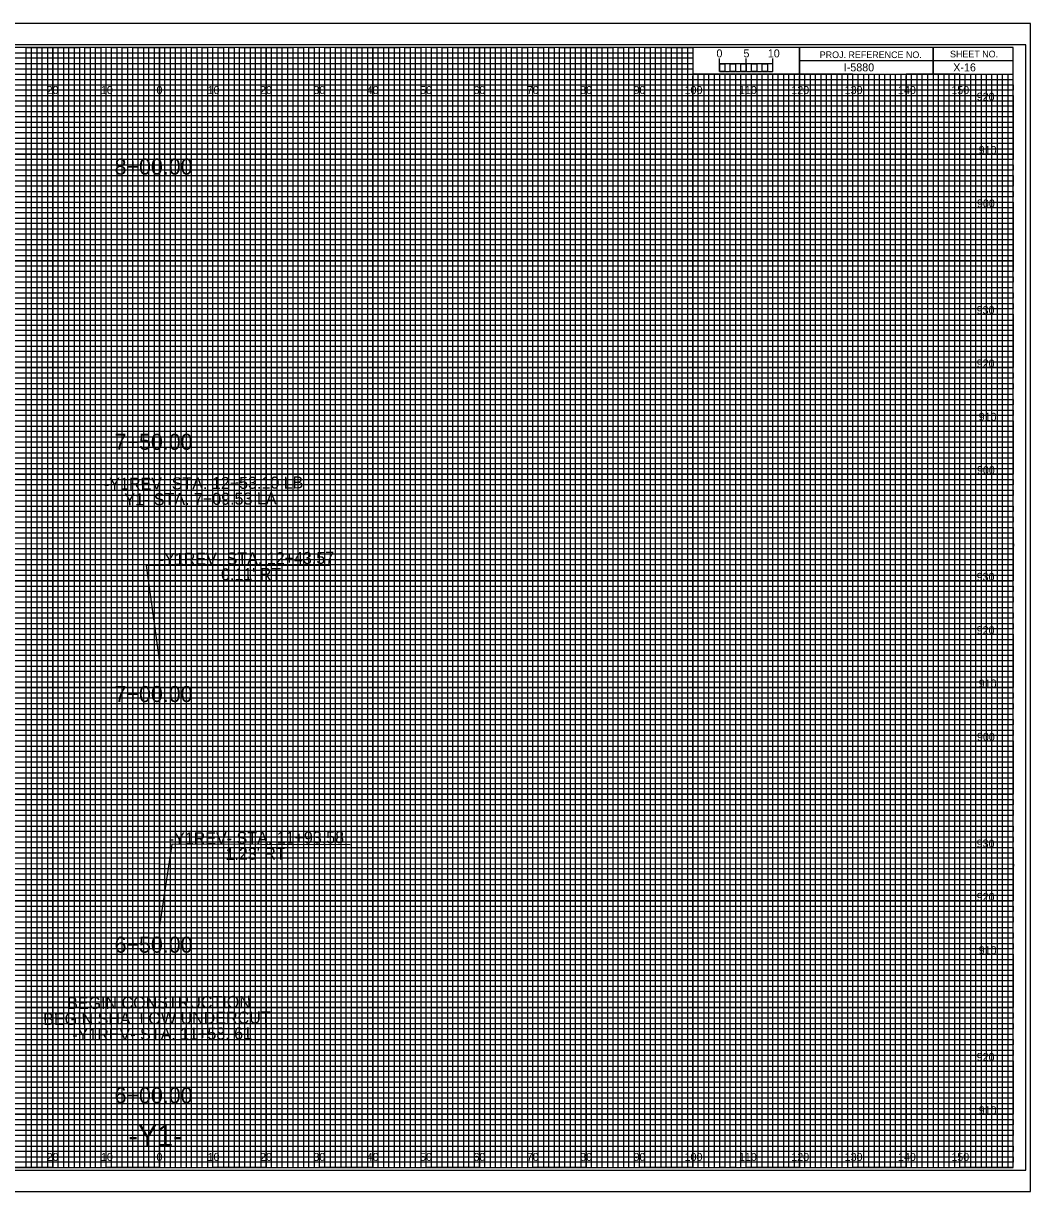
# Model space of a CAD drawing. Extents: x -13 to 323, y -4 to 214.
# Drawn here: x 134.5 to 323.3, y -4.5 to 214.5 of the extents above; entities that cross this region are included whole.
import ezdxf

# ---------------------------------------------------------------- set-up
doc = ezdxf.new("R2010")
doc.units = 0
for name, color, linetype in [('Exist XS Center Line Elevation Label', 7, 'Continuous'), ('Prop XS Alignment Label', 7, 'Continuous'), ('Prop XS Bar Scale Labels', 7, 'Continuous'), ('Prop XS Elevation Labels', 7, 'Continuous'), ('Prop XS Project Number', 7, 'Continuous'), ('Prop XS SE Text', 7, 'Continuous'), ('Prop XS Sheet Number', 7, 'Continuous'), ('Prop XS Station Labels', 7, 'Continuous'), ('Sheet Cross Section CELL', 7, 'Continuous'), ('Sheet Cross Section Grid Major CELL', 7, 'Continuous'), ('Sheet Cross Section Grid Middle CELL', 7, 'Continuous'), ('Sheet Cross Section Grid Minor 1 CELL', 7, 'Continuous'), ('Sheet Cross Section Grid Minor 2 CELL', 7, 'Continuous'), ('Sheet Cross Section Scale CELL', 7, 'Continuous'), ('Sheet Cutting Line CELL', 7, 'Continuous'), ('Sheet DOT Grid CELL', 7, 'Continuous'), ('Sheet Plot Border Inside CELL', 7, 'Continuous'), ('Sheet Plot Border Outside CELL', 7, 'Continuous')]:
    doc.layers.add(name, color=color, linetype=linetype)

msp = doc.modelspace()

# ---------------------------------------------------------------- linework, layer by layer
at = {"layer": 'Prop XS SE Text'}
for p, q in [((191.87, 112.88), (157.52, 112.88)), ((157.52, 112.88), (160, 94.74)), ((162.31, 60.64), (160, 45.32)), ((195.77, 60.51), (162.31, 60.64))]:
    msp.add_line(p, q, dxfattribs=at)
at = {"layer": 'Sheet Cross Section CELL'}
for p, q in [((305, 210), (305, 205)), ((305, 205), (305, 210)), ((280, 207.5), (280, 205)), ((320, 207.49), (280, 207.49)), ((280, 205), (320, 205))]:
    msp.add_line(p, q, dxfattribs=at)
for points in [[(320, 210), (0, 210), (0, 0), (320, 0)], [(280, 210), (260, 210), (260, 205.03), (280, 205.03)], [(320, 210), (280, 210), (280, 205), (320, 205)]]:
    msp.add_lwpolyline(points, close=True, dxfattribs=at)
at = {"layer": 'Sheet Cross Section Grid Major CELL'}
for p, q in [((150, 210), (140, 210)), ((140, 210), (140, 0)), ((150, 0), (150, 210)), ((170, 210), (160, 210)), ((160, 210), (160, 0)), ((170, 0), (170, 210)), ((190, 210), (180, 210)), ((180, 210), (180, 0)), ((190, 0), (190, 210)), ((210, 210), (200, 210)), ((200, 210), (200, 0)), ((210, 0), (210, 210)), ((230, 210), (220, 210)), ((220, 210), (220, 0)), ((230, 0), (230, 210)), ((250, 210), (240, 210)), ((240, 210), (240, 0)), ((250, 0), (250, 210)), ((260, 210), (260, 0)), ((270, 0), (270, 205)), ((290, 205), (280, 205)), ((280, 205), (280, 0)), ((290, 0), (290, 205)), ((310, 205), (300, 205)), ((300, 205), (300, 0)), ((310, 0), (310, 205)), ((140, 0), (130, 0)), ((160, 0), (150, 0)), ((180, 0), (170, 0)), ((200, 0), (190, 0)), ((220, 0), (210, 0)), ((240, 0), (230, 0)), ((260, 0), (250, 0)), ((280, 0), (270, 0)), ((300, 0), (290, 0)), ((320, 0), (310, 0)), ((320, 0), (320, 0))]:
    msp.add_line(p, q, dxfattribs=at)
for points in [[(0, 200), (320, 200), (320, 190), (0, 190)], [(0, 180), (320, 180), (320, 170), (0, 170)], [(0, 160), (320, 160), (320, 150), (0, 150)], [(0, 140), (320, 140), (320, 130), (0, 130)], [(0, 120), (320, 120), (320, 110), (0, 110)], [(0, 100), (320, 100), (320, 90), (0, 90)], [(0, 80), (320, 80), (320, 70), (0, 70)], [(0, 60), (320, 60), (320, 50), (0, 50)], [(0, 40), (320, 40), (320, 30), (0, 30)], [(0, 20), (320, 20), (320, 10), (0, 10)]]:
    msp.add_lwpolyline(points, dxfattribs=at)
at = {"layer": 'Sheet Cross Section Grid Middle CELL'}
for points in [[(125, 0), (135, 0), (135, 210), (145, 210), (145, 0), (155, 0), (155, 210), (165, 210), (165, 0), (175, 0), (175, 210), (185, 210), (185, 0), (195, 0), (195, 210), (205, 210), (205, 0), (215, 0), (215, 210), (225, 210), (225, 0), (235, 0), (235, 210), (245, 210), (245, 0), (255, 0), (255, 210), (259.93, 210), (260, 210), (260, 205), (264.99, 205), (264.99, 0), (275, 0), (275, 205), (285, 205), (285, 0), (295, 0), (295, 205), (305, 205), (305, 0), (315, 0), (315, 205)], [(0, 205), (275, 205)], [(0, 185), (320, 185), (320, 195), (0, 195)], [(0, 165), (320, 165), (320, 175), (0, 175)], [(0, 145), (320, 145), (320, 155), (0, 155)], [(0, 125), (320, 125), (320, 135), (0, 135)], [(0, 105), (320, 105), (320, 115), (0, 115)], [(0, 85), (320, 85), (320, 95), (0, 95)], [(0, 65), (320, 65), (320, 75), (0, 75)], [(0, 45), (320, 45), (320, 55), (0, 55)], [(0, 25), (320, 25), (320, 35), (0, 35)], [(0, 5), (320, 5), (320, 15), (0, 15)]]:
    msp.add_lwpolyline(points, dxfattribs=at)
at = {"layer": 'Sheet Cross Section Grid Minor 1 CELL'}
for p, q in [((0, 209), (260, 209)), ((260, 209), (260, 207.98)), ((260, 207.98), (0, 207.98)), ((0, 207), (260, 207)), ((260, 205.89), (0, 205.89)), ((260, 207), (260, 205.89)), ((0, 204), (320, 204))]:
    msp.add_line(p, q, dxfattribs=at)
for points in [[(0, 203), (270, 203), (320, 203), (320, 202), (0, 202)], [(0, 201), (320, 201), (320, 199), (0, 199)], [(0, 198), (320, 198), (320, 197), (0, 196.98)], [(0, 196), (320, 196), (320, 194), (0, 194)], [(0, 193), (320, 193), (320, 192), (0, 192)], [(0, 191), (320, 191), (320, 189), (0, 189)], [(0, 188), (320, 188), (320, 187), (0, 187)], [(0, 186), (320, 186), (320, 184), (0, 184)], [(0, 183), (320, 183), (320, 182), (0, 182)], [(0, 181), (320, 181), (320, 179), (0, 179)], [(0, 178), (320, 178), (320, 177), (0, 177)], [(0, 176), (320, 176), (320, 173.95), (320, 173), (320, 172), (0, 172)], [(0, 174), (320, 174), (320, 173), (0, 173)], [(0, 171), (320, 171), (320, 169), (0, 169.03)], [(0, 169.03), (320, 169), (320, 168), (0, 168)], [(0, 167), (320, 167), (320, 166), (0, 166)], [(0, 164), (320, 164), (320, 163), (0, 163)], [(0, 162), (320, 162), (320, 161), (0, 161)], [(-0.07, 158.89), (320, 158.89), (320, 157.88), (-0.07, 157.88)], [(0, 157), (320, 157), (320, 156), (0, 156)], [(0, 154), (320, 154), (320, 153), (0, 153)], [(0, 152), (320, 152), (320, 151), (0, 151)], [(0, 149), (320, 149), (320, 148), (0, 148)], [(0, 147), (320, 147), (320, 146), (0, 146)], [(0, 144), (320, 144), (320, 143), (0, 143)], [(0, 142), (320, 142), (320, 141), (0, 141)], [(0, 139), (320, 139), (319.99, 137.98), (0, 138)], [(0, 137), (320, 137), (320, 136), (0, 136)], [(0, 134), (320, 134), (320, 133), (0, 133)], [(0, 132), (320, 132), (320, 131), (0, 131)], [(0, 129), (320, 129), (320, 128), (0, 128)], [(0, 127), (320, 127), (320, 126), (0, 126)], [(0, 124), (320, 124), (320, 123), (0, 123)], [(0, 122), (320, 122), (320, 121), (0, 121)], [(0, 119), (320, 119), (320, 118), (0, 118)], [(0, 116.99), (320.07, 116.91), (320, 116), (0, 116)], [(0, 114), (320, 114), (320, 113), (0, 113)], [(0, 112), (320, 112), (320, 111), (0, 111)], [(0, 109), (320, 109), (320, 108), (0, 108)], [(0, 107), (320, 107), (320, 106), (0, 106)], [(0, 104), (320, 104), (320, 103), (0, 103)], [(0, 102), (320, 102), (320, 101), (0, 101)], [(0, 99), (320, 99), (320, 98), (0, 98)], [(0, 97), (320, 97), (320, 96), (0, 96)], [(0, 94), (320, 94), (320, 93), (0, 93)], [(0, 92), (320, 92), (320, 91), (0, 91)], [(0, 89), (320, 89), (320, 88), (0, 88)], [(0, 87), (320, 87), (320, 86), (0, 86)], [(0, 84), (320, 84), (320, 83), (0, 83)], [(0, 82), (320, 82), (320, 81), (0, 81)], [(0, 79), (320, 79), (319.99, 77.98), (0, 78)], [(0, 77), (320, 77), (320, 76), (0, 76)], [(0, 74), (320, 74), (320, 73), (0, 73)], [(0, 72), (320, 72), (320, 71), (0, 71)], [(0, 69), (320, 69), (320, 68), (0, 68)], [(0, 67), (320, 67), (320, 66), (0, 66)], [(0, 64), (320, 64), (320, 63), (0, 63)], [(0, 62), (320, 62), (320, 61), (0, 61)], [(0, 59), (320, 59), (320, 58), (0, 58)], [(0, 56.99), (320.07, 56.91), (320, 56), (0, 56)], [(0, 54), (320, 54), (320, 53), (0, 53)], [(0, 52), (320, 52), (320, 51), (0, 51)], [(0, 49), (320, 49), (320, 48), (0, 48)], [(0, 47), (320, 47), (320, 46), (0, 46)], [(0, 44), (320, 44), (320, 43), (0, 43)], [(0, 42), (320, 42), (320, 41), (0, 41)], [(0, 39), (320, 39), (320, 38), (0, 38)], [(0, 37), (320, 37), (320, 36), (0, 36)], [(0, 34), (320, 34), (320, 33), (0, 33)], [(0, 32), (320, 32), (320, 31), (0, 31)], [(0, 29), (320, 29), (320, 28), (0, 28)], [(0, 27), (320, 27), (320, 26), (0, 26)], [(0, 24), (320, 24), (320, 23), (0, 23)], [(0, 22), (320, 22), (320, 21), (0, 21)], [(0, 19), (320, 19), (320, 18), (0, 18)], [(0, 17), (320, 17), (320, 16), (0, 16)], [(0, 14), (320, 14), (320, 13), (0, 13)], [(0, 12), (320, 12), (320, 11), (0, 11)], [(0, 9), (320, 9), (320, 8), (0, 8)], [(0, 7), (320, 7), (320, 6), (0, 6)], [(0, 4), (320, 4), (320, 3), (0, 3)], [(0, 2), (320, 2), (320, 1), (0, 1)]]:
    msp.add_lwpolyline(points, dxfattribs=at)
at = {"layer": 'Sheet Cross Section Grid Minor 2 CELL'}
for p, q in [((267, 205), (266.01, 205)), ((266.01, 205), (266.01, 0)), ((267, 0), (267, 205)), ((269, 205), (268, 205)), ((268, 205), (268, 0)), ((269, 0), (269, 205)), ((266.01, 0), (265, 0)), ((268, 0), (267, 0))]:
    msp.add_line(p, q, dxfattribs=at)
for points in [[(135, 0), (136, 0), (136, 210), (137, 210), (137, 0)], [(137, 0), (138, 0), (138, 210), (139, 210), (139, 0)], [(140, 0), (141, 0), (141, 210), (142, 210), (142, 0)], [(142, 0), (143, 0), (143, 210), (144, 210), (144, 0)], [(145, 0), (146, 0), (146, 210), (147, 210), (147, 0)], [(147, 0), (148, 0), (148, 210), (149, 210), (149, 0)], [(150, 0), (151, 0), (151, 210), (152, 210), (152, 0)], [(152, 0), (153, 0), (153, 210), (154, 210), (154, 0)], [(155, 0), (156, 0), (156, 210), (157, 210), (157, 0)], [(157, 0), (158, 0), (158, 210), (159, 210), (159, 0)], [(160, 0), (161, 0), (161, 210), (162, 210), (162, 0)], [(162, 0), (163, 0), (163, 210), (164, 210), (164, 0)], [(165, 0), (166, 0), (166, 210), (167, 210), (167, 0)], [(167, 0), (168, 0), (168, 210), (169, 210), (169, 0)], [(170, 0), (171, 0), (171, 210), (172, 210), (172, 0)], [(172, 0), (173, 0), (173, 210), (174, 210), (174, 0)], [(175, 0), (176, 0), (176, 210), (177, 210), (177, 0)], [(177, 0), (178, 0), (178, 210), (179, 210), (179, 0)], [(180, 0), (181, 0), (181, 210), (182, 210), (182, 0)], [(182, 0), (183, 0), (183, 210), (184, 210), (184, 0)], [(185, 0), (186, 0), (186, 210), (187, 210), (187, 0)], [(187, 0), (188, 0), (188, 210), (189, 210), (189, 0)], [(190, 0), (191, 0), (191, 210), (192, 210), (192, 0)], [(192, 0), (193, 0), (193, 210), (194, 210), (194, 0)], [(195, 0), (196, 0), (196, 210), (197, 210), (197, 0)], [(197, 0), (198, 0), (198, 210), (199, 210), (199, 0)], [(200, 0), (201, 0), (201, 210), (202, 210), (202, 0)], [(202, 0), (203, 0), (203, 210), (204, 210), (204, 0)], [(205, 0), (206, 0), (206, 210), (207, 210), (207, 0)], [(207, 0), (208, 0), (208, 210), (209, 210), (209, 0)], [(210, 0), (211, 0), (211, 210), (212, 210), (212, 0)], [(212, 0), (213, 0), (213, 210), (214, 210), (214, 0)], [(215, 0), (216, 0), (216, 210), (217, 210), (217, 0)], [(217, 0), (218, 0), (218, 210), (219, 210), (219, 0)], [(220, 0), (221, 0), (221, 210), (222, 210), (222, 0)], [(222, 0), (223, 0), (223, 210), (224, 210), (224, 0)], [(225, 0), (226, 0), (226, 210), (227, 210), (227, 0)], [(227, 0), (228, 0), (228, 210), (229, 210), (229, 0)], [(230, 0), (231, 0), (231, 210), (232, 210), (232, 0)], [(232, 0), (233, 0), (233, 210), (234, 210), (234, 0)], [(235, 0), (236, 0), (236, 210), (237, 210), (237, 0)], [(237, 0), (238, 0), (238, 210), (239, 210), (239, 0)], [(240, 0), (241, 0), (241, 210), (242, 210), (242, 0)], [(242, 0), (243, 0), (243, 210), (244, 210), (244, 0)], [(245, 0), (246, 0), (246, 210), (247, 210), (247, 0)], [(247, 0), (248, 0), (248, 210), (249, 210), (249, 0)], [(250, 0), (251, 0), (251, 210), (252, 210), (252, 0)], [(252, 0), (253, 0), (253, 210), (254, 210), (254, 0)], [(255, 0), (256, 0), (256, 210), (257, 210), (257, 0)], [(257, 0), (258, 0), (258, 210), (259, 210), (259, 0)], [(260, 0), (261, 0), (261, 205), (262.02, 205), (262.02, 0)], [(262, 0), (263, 0), (263, 205), (263.99, 205), (263.99, 0)], [(270, 0), (270.98, 0), (270.98, 205), (272, 205), (272, 0)], [(272, 0), (273, 0), (273, 205), (274.05, 205), (274.05, 0)], [(275, 0), (276, 0), (276, 205), (277, 205), (277, 0)], [(277, 0), (278, 0), (278, 205), (279, 205), (279, 0)], [(280, 0), (281, 0), (281, 205), (282, 205), (282, 0)], [(282, 0), (283, 0), (283, 205), (284, 205), (284, 0)], [(285, 0), (286, 0), (286, 205), (287, 205), (287, 0)], [(287, 0), (288, 0), (288, 205), (289, 205), (289, 0)], [(290, 0), (291, 0), (291, 205), (292, 205), (292, 0)], [(292, 0), (293, 0), (293, 205), (294, 205), (294, 0)], [(295, 0), (296, 0), (296, 205), (297, 205), (297, 0)], [(297, 0), (298, 0), (298, 205), (299, 205), (299, 0)], [(300, 0), (301, 0), (301, 205), (302, 205), (302, 0)], [(302, 0), (303, 0), (303, 205), (304, 205), (304, 0)], [(305, 0), (306, 0), (306, 205), (307, 205), (307, 0)], [(307, 0), (308, 0), (308, 205), (309, 205), (309, 0)], [(310, 0), (311, 0), (311, 205), (312, 205), (312, 0)], [(312, 0), (313, 0), (313, 205), (314, 205), (314, 0)], [(315, 0), (316, 0), (316, 205), (317, 205), (317, 0)], [(317, 0), (318, 0), (318, 205), (319, 205), (319, 0)]]:
    msp.add_lwpolyline(points, dxfattribs=at)
at = {"layer": 'Sheet Cross Section Scale CELL'}
for p, q in [((265, 205.49), (265, 207.9)), ((265, 206.9), (265, 207.9)), ((270, 205.49), (270, 207.9)), ((275, 205.49), (275, 207.9)), ((275, 206.9), (275, 207.9))]:
    msp.add_line(p, q, dxfattribs=at)
for points in [[(275, 206.9), (265, 206.9), (265, 205.49), (275, 205.49)], [(265, 206.9), (266, 206.9), (266, 205.49), (265, 205.49)], [(267, 206.9), (268, 206.9), (268, 205.49), (267, 205.49)], [(269, 206.9), (270, 206.9), (270, 205.49), (269, 205.49)], [(271, 206.9), (272, 206.9), (272, 205.49), (271, 205.49)], [(273, 206.9), (274, 206.9), (274, 205.49), (273, 205.49)]]:
    msp.add_lwpolyline(points, close=True, dxfattribs=at)
at = {"layer": 'Sheet Cutting Line CELL'}
for p, q in [((323.3, 214.5), (-13.4, 214.5)), ((-13.4, -4.5), (323.3, -4.5))]:
    msp.add_line(p, q, dxfattribs=at)
at = {"layer": 'Sheet DOT Grid CELL'}
for p, q in [((140, 0), (140, 210)), ((150, 0), (150, 210)), ((160, 0), (160, 210)), ((170, 0), (170, 210)), ((180, 0), (180, 210)), ((190, 0), (190, 210)), ((200, 0), (200, 210)), ((210, 0), (210, 210)), ((220, 0), (220, 210)), ((230, 0), (230, 210)), ((240, 0), (240, 210)), ((250, 0), (250, 210)), ((260, 0), (260, 204.69)), ((270, 0), (270, 204.69)), ((280, 0), (280, 204.69)), ((290, 0), (290, 204.69)), ((300, 0), (300, 204.69)), ((310, 0), (310, 204.69)), ((0, 200), (320, 200)), ((0, 190), (320, 190)), ((0, 180), (320, 180)), ((0, 170), (320, 170)), ((0, 160), (320, 160)), ((0, 150), (320, 150)), ((0, 140), (320, 140)), ((0, 130), (320, 130)), ((0, 120), (320, 120)), ((0, 110), (320, 110)), ((0, 100), (320, 100)), ((0, 90), (320, 90)), ((0, 80), (320, 80)), ((0, 70), (320, 70)), ((0, 60), (320, 60)), ((0, 50), (320, 50)), ((0, 40), (320, 40)), ((0, 30), (320, 30)), ((0, 20), (320, 20)), ((0, 10), (320, 10))]:
    msp.add_line(p, q, dxfattribs=at)
at = {"layer": 'Sheet Plot Border Inside CELL'}
msp.add_lwpolyline([(-10.8, -0.5), (322.4, -0.5), (322.4, 210.5), (-10.8, 210.5)], close=True, dxfattribs=at)
at = {"layer": 'Sheet Plot Border Outside CELL'}
msp.add_lwpolyline([(-13.4, -4.5), (323.3, -4.5), (323.3, 214.5), (-13.4, 214.5)], close=True, dxfattribs=at)

# ---------------------------------------------------------------- texts
at = {"layer": 'Exist XS Center Line Elevation Label'}
for s, p in [('20', (138.86, 201.25)), ('10', (149.04, 201.25)), ('0', (159.45, 201.25)), ('0', (159.45, 201.25)), ('10', (169.04, 201.25)), ('20', (178.86, 201.25)), ('30', (188.86, 201.25)), ('40', (198.86, 201.25)), ('50', (208.86, 201.25)), ('60', (218.86, 201.25)), ('70', (228.86, 201.25)), ('80', (238.86, 201.25)), ('90', (248.86, 201.25)), ('100', (258.44, 201.25)), ('110', (268.62, 201.25)), ('120', (278.44, 201.25)), ('130', (288.44, 201.25)), ('140', (298.44, 201.25)), ('150', (308.44, 201.25)), ('20', (138.86, 1.25)), ('10', (149.04, 1.25)), ('0', (159.45, 1.25)), ('0', (159.45, 1.25)), ('10', (169.04, 1.25)), ('20', (178.86, 1.25)), ('30', (188.86, 1.25)), ('40', (198.86, 1.25)), ('50', (208.86, 1.25)), ('60', (218.86, 1.25)), ('70', (228.86, 1.25)), ('80', (238.86, 1.25)), ('90', (248.86, 1.25)), ('100', (258.44, 1.25)), ('110', (268.62, 1.25)), ('120', (278.44, 1.25)), ('130', (288.44, 1.25)), ('140', (298.44, 1.25)), ('150', (308.44, 1.25))]:
    msp.add_text(s, height=1.5, dxfattribs=at).set_placement(p)
at = {"layer": 'Prop XS Alignment Label'}
msp.add_text('-Y1-', height=4, dxfattribs=at).set_placement((154.21, 4))
at = {"layer": 'Prop XS Bar Scale Labels'}
for s, p in [('5', (269.47, 208.12)), ('10', (274.04, 208.12))]:
    msp.add_text(s, height=1.5, dxfattribs=at).set_placement(p)
at = {"layer": 'Prop XS Elevation Labels'}
for s, p in [('920', (313.19, 200)), ('910', (313.57, 190)), ('900', (313.24, 180)), ('930', (313.18, 160)), ('920', (313.19, 150)), ('910', (313.57, 140)), ('900', (313.24, 130)), ('930', (313.18, 110)), ('920', (313.19, 100)), ('910', (313.57, 90)), ('900', (313.24, 80)), ('930', (313.18, 60)), ('920', (313.19, 50)), ('910', (313.57, 40)), ('920', (313.19, 20)), ('910', (313.57, 10))]:
    msp.add_text(s, height=1.5, dxfattribs=at).set_placement(p)
at = {"layer": 'Prop XS Project Number'}
msp.add_text('I-5880', height=1.5, dxfattribs=at).set_placement((288.28, 205.5))
at = {"layer": 'Prop XS SE Text'}
for s, p in [('-Y1REV- STA. 12+53.10 LB', (149.61, 127.05)), ('-Y1- STA. 7+09.53 LA', (152.44, 124.12)), ('-Y1REV- STA. 12+43.57', (159.9, 112.96)), ("0.11' RT", (171.56, 110.09)), ('-Y1REV- STA. 11+93.58', (161.76, 60.56)), ("1.23' RT.", (172.39, 57.68)), ('BEGIN CONSTRUCTION', (142.71, 29.71)), ('BEGIN SHALLOW UNDERCUT', (138.22, 26.73)), ('-Y1REV- STA. 11+58. 61', (143.67, 23.82))]:
    msp.add_text(s, height=2.25, rotation=0.4127, dxfattribs=at).set_placement(p)
at = {"layer": 'Prop XS Sheet Number'}
msp.add_text('X-16', height=1.5, dxfattribs=at).set_placement((308.8, 205.5))
at = {"layer": 'Prop XS Station Labels'}
for s, p in [('8+00.00', (151.6, 186.15)), ('7+50.00', (151.6, 134.56)), ('7+00.00', (151.6, 87.28)), ('6+50.00', (151.6, 40.29)), ('6+00.00', (151.6, 12.06))]:
    msp.add_text(s, height=3, dxfattribs=at).set_placement(p)
at = {"layer": 'Sheet Cross Section CELL'}
for s, p in [('PROJ. REFERENCE NO.', (283.77, 207.99)), ('SHEET NO.', (308.19, 208.12))]:
    msp.add_text(s, height=1.25, dxfattribs=at).set_placement(p)
at = {"layer": 'Sheet Cross Section Scale CELL'}
msp.add_text('0', height=1.5, dxfattribs=at).set_placement((264.41, 208.12))

doc.saveas('drawing.dxf')
